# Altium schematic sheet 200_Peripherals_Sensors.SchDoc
size A; SheetNumber: 4; SheetTotal: 5
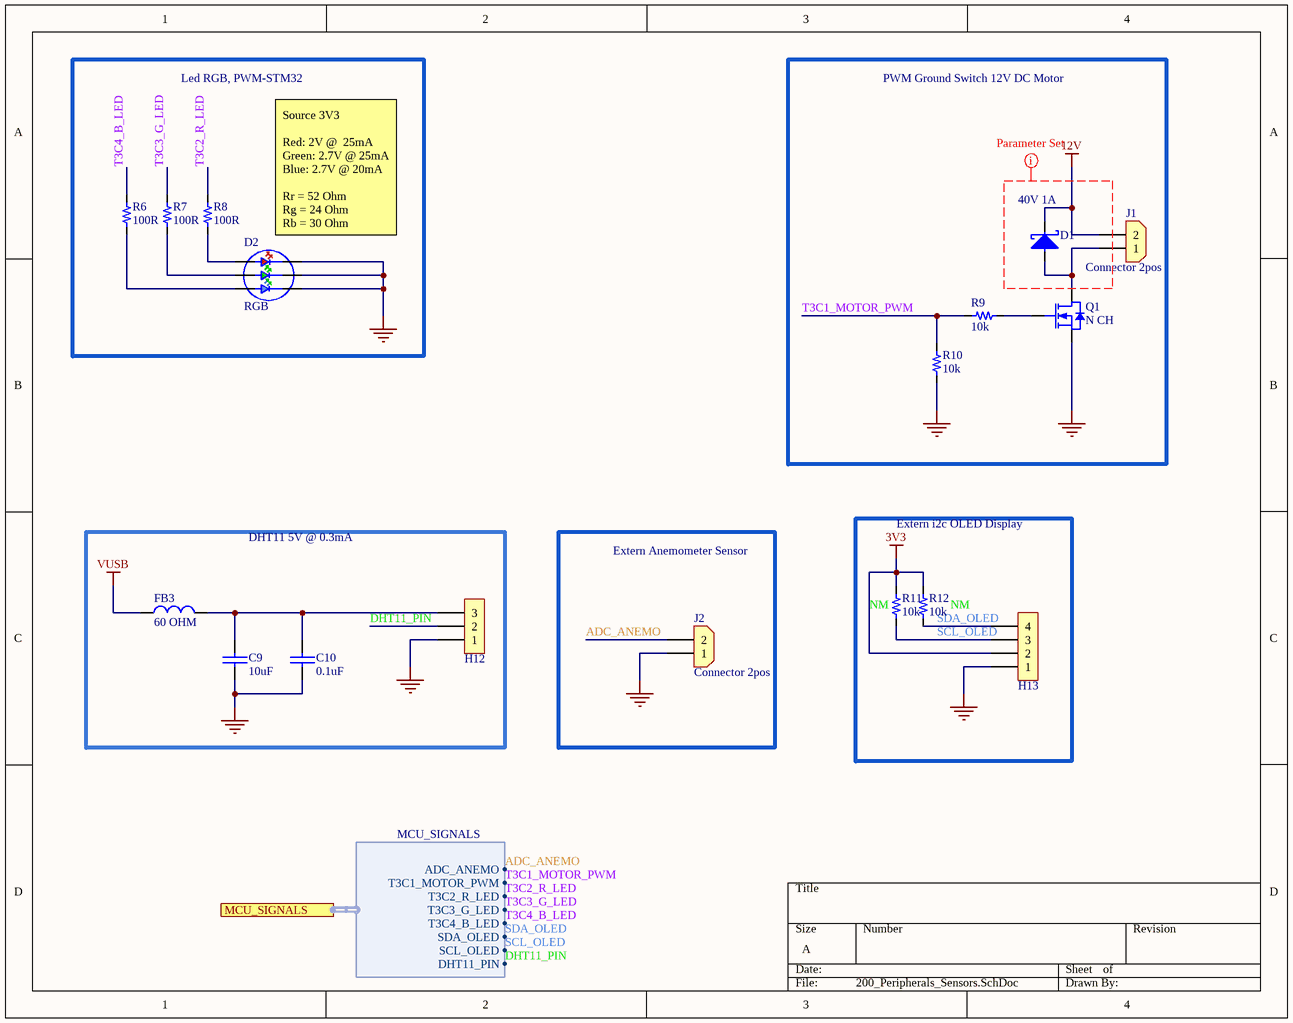
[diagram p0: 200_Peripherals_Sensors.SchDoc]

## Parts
C9  value 10uF  [0805_cap]  (hidden comment: 10uF 25V)
C10  value 0.1uF  [0603_cap]  (hidden comment: 0.1uF 50V)
D1  40V 1A  [SOD_123]
D2  RGB  [RGB_NS_3.5X3.7]
FB3  value 60 OHM  [0603_fb]  (hidden comment: 60OHM 2A)
H12  3x1  [H_3X1_TH_100mil]  (value not drawn)  (no BOM)
H13  4x1  [H_4x1_TH_2.54mm]  (value not drawn)  (no BOM)
J1  Connector 2pos  [CON_2x1_TH_5MM]
J2  Connector 2pos  [CON_2x1_TH_5MM]
Q1  N CH  [SOT_23_3]
R6  value 100R  [0603_res]  (hidden comment: 100R 1/10W)
R7  value 100R  [0603_res]  (hidden comment: 100R 1/10W)
R8  value 100R  [0603_res]  (hidden comment: 100R 1/10W)
R9  value 10k  [0603_res]  (hidden comment: 10k 1/10W)
R10  value 10k  [0603_res]  (hidden comment: 10k 1/10W)
R11  value 10k  Usage: NM  [0603_res]  (hidden comment: 10k 1/10W)
R12  value 10k  Usage: NM  [0603_res]  (hidden comment: 10k 1/10W)

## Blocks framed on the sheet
Led RGB, PWM-STM32: D2 R6-R8
PWM Ground Switch 12V DC Motor: D1 J1 Q1 R9 R10
DHT11 5V @ 0.3mA: C9 C10 FB3 H12
Extern Anemometer Sensor: J2
Extern i2c OLED Display: H13 R11 R12

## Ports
MCU_SIGNALS (harness MCU_SIGNALS, see Main[3B], 000_STM[3D])

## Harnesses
MCU_SIGNALS: ADC_ANEMO, T3C1_MOTOR_PWM, T3C2_R_LED, T3C3_G_LED, T3C4_B_LED, SDA_OLED, SCL_OLED, DHT11_PIN

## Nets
3V3: H13.2 R11.2 R12.2
12V: D1.1 J1.2
GND: C9.2 C10.2 D2.1 D2.2 D2.3 H12.1 H13.1 J2.1 Q1.2(S) R10.1
VUSB: FB3.1
ADC_ANEMO: J2.2 ; port MCU_SIGNALS.ADC_ANEMO
DHT11_PIN: H12.2 ; port MCU_SIGNALS.DHT11_PIN
SCL_OLED: H13.3 R11.1 ; port MCU_SIGNALS.SCL_OLED
SDA_OLED: H13.4 R12.1 ; port MCU_SIGNALS.SDA_OLED
T3C1_MOTOR_PWM: R9.2 R10.2 ; port MCU_SIGNALS.T3C1_MOTOR_PWM
T3C2_R_LED: R8.2 ; port MCU_SIGNALS.T3C2_R_LED
T3C3_G_LED: R7.2 ; port MCU_SIGNALS.T3C3_G_LED
T3C4_B_LED: R6.2 ; port MCU_SIGNALS.T3C4_B_LED
NetC9_1: C9.1 C10.1 FB3.2 H12.3
NetD1_2: D1.2 J1.1 Q1.3(D)
NetD2_4: D2.4 R8.1
NetD2_5: D2.5 R7.1
NetD2_6: D2.6 R6.1
NetQ1_1: Q1.1(G) R9.1

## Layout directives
net class 12V_2A: (no net found under the mark)

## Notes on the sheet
- (near D2) Source 3V3
  Red: 2V @  25mA
  Green: 2.7V @ 25mA
  Blue: 2.7V @ 20mA
  Rr = 52 Ohm
  Rg = 24 Ohm
  Rb = 30 Ohm

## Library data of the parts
C9 = Cap_10uF_0805_25V_: 25V 10uF X5R ±10% 0805 Multilayer Ceramic Capacitors MLCC - SMD/SMT ROHS; Manufacturer: Samsung Electro-Mechanics; Manufacturer Part Number: CL21A106KAYNNNE
C10 = Cap_0.1uF_0603_50V: 50V 100nF Y5V -20%~+80% 0603 Multilayer Ceramic Capacitors MLCC - SMD/SMT ROHS; Manufacturer: Walsin Tech Corp; Manufacturer Part Number: 0603F104Z500CT
D1 = D_Schottky_40V_1A_SOD_123F: DIODE SCHOTTKY 40V 1A SOD123F; Manufacturer: Shanghai Prisemi Elec; Manufacturer Part Number: PSBD1DF40V1H
D2 = LED_RGB_3535_SMD: -30℃~+85℃ RGB 110° 3535(mm) Light Emitting Diodes (LED) ROHS; Manufacturer: Foshan NationStar Optoelectronics; Manufacturer Part Number: RS-3535MWAM
FB3 = FB_60_0603_2A: 2A 1 100mΩ 60Ω@100MHz ±25% 0603 Ferrite Beads ROHS; Manufacturer: TAI-TECH; Manufacturer Part Number: HCB1608KF-600T20
H12 = H_Male_3x1_TH_100mil
H13 = H_Male_4x1_TH_100mil
J1 J2 = Con_2x1_TH_5mm: 2POS 5MM; Manufacturer: JILN; Manufacturer Part Number: JL126-50002G01
Q1 = Q_NFET_20V_3.2A_SOT23: MOSFET N-CH 20V SOT23; Manufacturer: Doeshare; Manufacturer Part Number: DN2302S
R6-R8 = Res_100R_0603_1/10W: RES SMD 100R OHM 5% 1/10W 0603; Manufacturer: FOJAN; Manufacturer Part Number: FRC0603J101 TS
R9-R12 = Res_10k_0603_1/10W: RES SMD 10k OHM 5% 1/10W 0603; Manufacturer: FOJAN; Manufacturer Part Number: FRC0603J103TS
